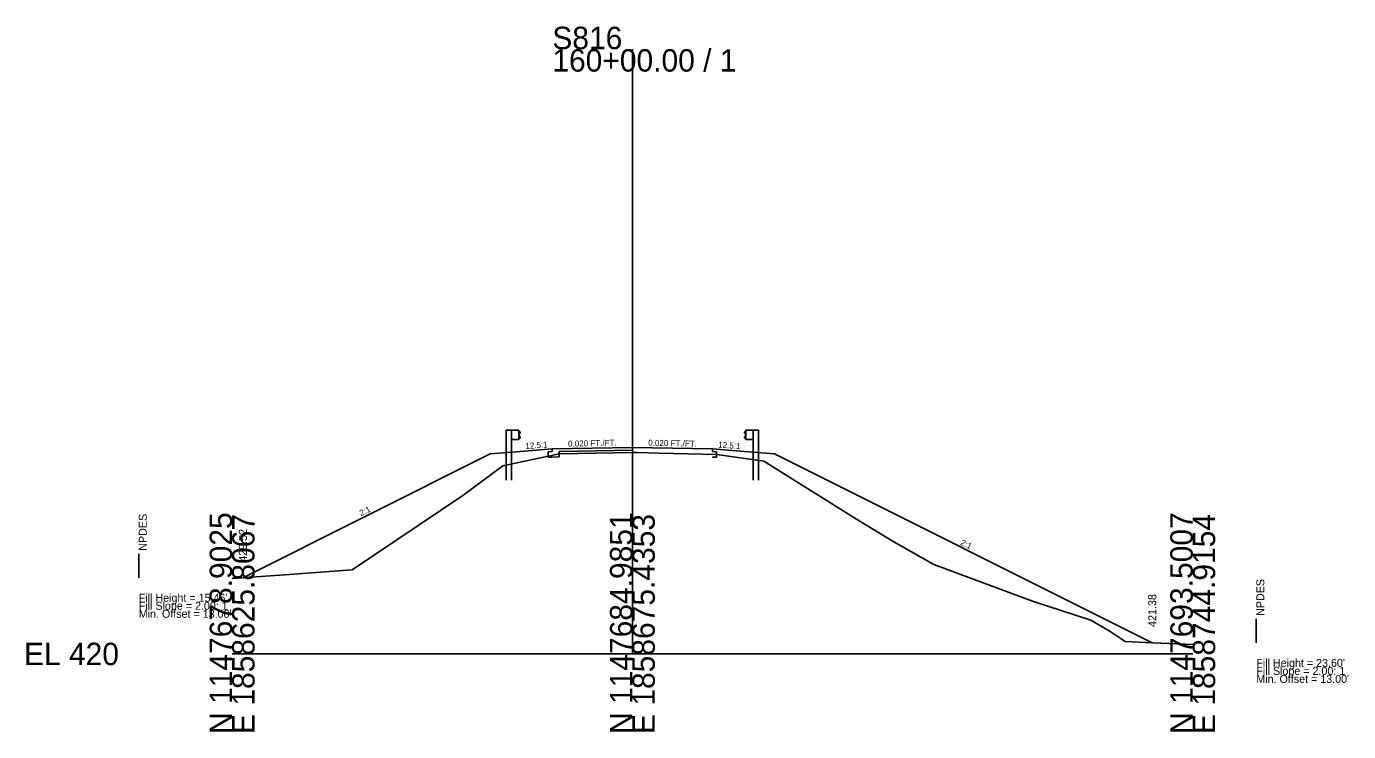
# Model space of a CAD drawing. Extents: x -76 to 4323, y -10 to 2055.
# Drawn here: x 3074.3 to 3239.5, y 490.3 to 578.4 of the extents above; entities that cross this region are included whole.
import ezdxf

# ---------------------------------------------------------------- set-up
doc = ezdxf.new("R2010")
doc.units = 0
for name, color, linetype in [('Default', 7, 'Continuous'), ('RD_GPK_XS_Cell', 7, 'Continuous'), ('RD_XS_Base', 7, 'Continuous'), ('RD_XS_Buildup', 7, 'Continuous'), ('RD_XS_EarthShd', 7, 'Continuous'), ('RD_XS_ExGround', 7, 'Continuous'), ('RD_XS_GR', 7, 'Continuous'), ('RD_XS_NPDES', 7, 'Continuous'), ('RD_XS_Pave', 7, 'Continuous'), ('RD_XS_TieSlope', 7, 'Continuous'), ('RD_XS_TX_Elev_PR', 7, 'Continuous'), ('RD_XS_TX_ShdSlope', 7, 'Continuous'), ('RD_XS_TX_Slope', 7, 'Continuous'), ('RD_XS_TX_Warning', 7, 'Continuous')]:
    doc.layers.add(name, color=color, linetype=linetype)

msp = doc.modelspace()

# ---------------------------------------------------------------- linework, layer by layer
at = {"layer": 'Default'}
for p, q in [((3140, 525.6), (3150, 525.8)), ((3150, 525.8), (3160, 525.6))]:
    msp.add_line(p, q, dxfattribs=at)
at = {"layer": 'RD_GPK_XS_Cell'}
for p, q in [((3150, 500), (3150, 575.54)), ((3100, 500), (3150, 500)), ((3150, 500), (3220, 500))]:
    msp.add_line(p, q, dxfattribs=at)
at = {"layer": 'RD_XS_Base'}
for p, q in [((3140, 524.6), (3140.86, 524.62)), ((3140.86, 524.62), (3140.86, 525.01))]:
    msp.add_line(p, q, dxfattribs=at)
at = {"layer": 'RD_XS_Buildup'}
for p, q in [((3140.86, 525.29), (3150, 525.47)), ((3140.86, 525.01), (3140.86, 525.29))]:
    msp.add_line(p, q, dxfattribs=at)
at = {"layer": 'RD_XS_EarthShd'}
for p, q in [((3136, 525.28), (3132.25, 524.98)), ((3140, 525.6), (3136, 525.28)), ((3160, 525.6), (3164, 525.28)), ((3164, 525.28), (3167.75, 524.98))]:
    msp.add_line(p, q, dxfattribs=at)
at = {"layer": 'RD_XS_ExGround'}
for p, q in [((3133.81, 523.51), (3140.86, 525.01)), ((3140.86, 525.01), (3150, 525.17)), ((3150, 525.17), (3150.55, 525.18)), ((3150.55, 525.18), (3153.35, 525.1)), ((3153.35, 525.1), (3160.53, 524.91)), ((3160.53, 524.91), (3166.41, 524.08)), ((3166.41, 524.08), (3178.01, 516.83)), ((3128.8, 519.8), (3133.81, 523.51)), ((3115, 510.5), (3128.8, 519.8)), ((3178.01, 516.83), (3182.64, 513.99)), ((3182.64, 513.99), (3187.67, 511.17)), ((3106.53, 509.89), (3115, 510.5)), ((3187.67, 511.17), (3199.99, 506.59)), ((3100, 509.43), (3106.53, 509.89)), ((3199.99, 506.59), (3207.28, 504.22)), ((3207.28, 504.22), (3209.57, 502.88)), ((3209.57, 502.88), (3211.55, 501.56)), ((3211.55, 501.56), (3215.02, 501.38)), ((3215.02, 501.38), (3220, 501.16))]:
    msp.add_line(p, q, dxfattribs=at)
at = {"layer": 'RD_XS_GR'}
for p, q in [((3134.25, 527.94), (3134.25, 525.14)), ((3134.92, 527.94), (3134.25, 527.94)), ((3134.92, 527.94), (3134.92, 525.19)), ((3135.83, 527.94), (3134.92, 527.94)), ((3135.83, 526.77), (3135.83, 527.94)), ((3135.83, 527.86), (3136, 527.66)), ((3136, 527.61), (3135.83, 527.41)), ((3136, 527.09), (3135.83, 527.29)), ((3135.83, 526.84), (3136, 527.04)), ((3136, 527.66), (3136, 527.61)), ((3136, 527.04), (3136, 527.09)), ((3164.17, 527.86), (3164, 527.66)), ((3164, 527.66), (3164, 527.61)), ((3164, 527.61), (3164.17, 527.41)), ((3164, 527.09), (3164.17, 527.29)), ((3164, 527.04), (3164, 527.09)), ((3164.17, 526.84), (3164, 527.04)), ((3164.17, 526.77), (3164.17, 527.94)), ((3164.17, 527.94), (3165.08, 527.94)), ((3165.08, 527.94), (3165.08, 525.19)), ((3165.08, 527.94), (3165.75, 527.94)), ((3165.75, 527.94), (3165.75, 525.14)), ((3135.83, 526.77), (3134.92, 526.77)), ((3164.17, 526.77), (3165.08, 526.77)), ((3134.25, 525.14), (3134.25, 521.72)), ((3134.92, 521.72), (3134.92, 525.19)), ((3165.08, 521.72), (3165.08, 525.19)), ((3165.75, 525.14), (3165.75, 521.72))]:
    msp.add_line(p, q, dxfattribs=at)
at = {"layer": 'RD_XS_NPDES'}
for p, q in [((3088.34, 509.52), (3088.34, 512.52)), ((3227.94, 501.38), (3227.94, 504.38))]:
    msp.add_line(p, q, dxfattribs=at)
at = {"layer": 'RD_XS_Pave'}
for p, q in [((3139.5, 525.26), (3140, 525.27)), ((3139.5, 524.59), (3139.5, 525.26)), ((3140, 525.27), (3140, 525.6)), ((3160, 525.27), (3160, 525.6)), ((3160.5, 525.26), (3160, 525.27)), ((3160.5, 524.59), (3160.5, 525.26)), ((3140, 524.6), (3139.5, 524.59)), ((3160, 524.6), (3160.5, 524.59))]:
    msp.add_line(p, q, dxfattribs=at)
at = {"layer": 'RD_XS_TieSlope'}
for p, q in [((3132.25, 524.98), (3101.34, 509.52)), ((3167.75, 524.98), (3214.94, 501.38))]:
    msp.add_line(p, q, dxfattribs=at)

# ---------------------------------------------------------------- texts
at = {"layer": 'RD_GPK_XS_Cell'}
for s, p in [('S816', (3140, 575.54)), ('160+00.00 / 1', (3140, 572.74)), ('EL 420', (3074, 498.6))]:
    msp.add_text(s, height=2.8, dxfattribs=at).set_placement(p)
for s, p in [('N 1147678.9025', (3100, 490)), ('E 1858625.8067', (3102.8, 490)), ('N 1147684.9851', (3150, 490)), ('E 1858675.4353', (3152.8, 490)), ('N 1147693.5007', (3220, 490)), ('E 1858744.9154', (3222.8, 490))]:
    msp.add_text(s, height=2.8, rotation=90, dxfattribs=at).set_placement(p)
at = {"layer": 'RD_XS_TX_Elev_PR'}
for s, p in [('429.52', (3101.84, 511.52)), ('421.38', (3215.44, 503.38))]:
    msp.add_text(s, height=1, rotation=90, dxfattribs=at).set_placement(p)
at = {"layer": 'RD_XS_TX_ShdSlope'}
for rotation, p in [(4.5739, (3136.66, 525.58)), (355.4261, (3160.7, 525.79))]:
    msp.add_text('12.5:1', height=0.75, rotation=rotation, dxfattribs=at).set_placement(p)
at = {"layer": 'RD_XS_TX_Slope'}
for s, rotation, p in [('0.020 FT./FT.', 1.1458, (3141.97, 525.89)), ('0.020 FT./FT.', 358.8542, (3151.98, 526.01)), ('2:1', 26.5651, (3116.13, 517.2)), ('2:1', 333.4349, (3190.91, 513.68))]:
    msp.add_text(s, height=0.75, rotation=rotation, dxfattribs=at).set_placement(p)
at = {"layer": 'RD_XS_TX_Warning'}
for p in [(3089.34, 512.52), (3228.94, 504.38)]:
    msp.add_text(' NPDES', height=1, rotation=90, dxfattribs=at).set_placement(p)
for s, p in [("Fill Height = 15.46' ", (3088.34, 506.52)), ('Fill Slope = 2.00: 1', (3088.34, 505.52)), ("Min. Offset = 13.00' ", (3088.34, 504.52)), ("Fill Height = 23.60' ", (3227.94, 498.38)), ('Fill Slope = 2.00: 1', (3227.94, 497.38)), ("Min. Offset = 13.00' ", (3227.94, 496.38))]:
    msp.add_text(s, height=1, dxfattribs=at).set_placement(p)

doc.saveas('drawing.dxf')
